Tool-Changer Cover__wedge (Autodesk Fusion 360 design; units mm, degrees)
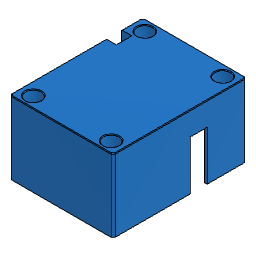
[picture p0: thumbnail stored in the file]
base_feature "Basiselement"
delete_face "Fläche löschen1"
delete_face "Fläche löschen2"
chamfer "Fase" distance 0.25
extrude "Extrusion1" sketch "unnamed" blind -0.6
extrude "Extrusion2" new body of existing geometry blind 0.6
sketch "Skizze1" plane through (0, 0, 1) normal (0, 0, 1) x axis (-1, 0, 0)
  line L1 (-19.0964, -39.75) -> (-19.75, -39.0964)
  line L2 (19.0964, -39.75) -> (-19.0964, -39.75)
  line L3 (19.75, -39.0964) -> (19.0964, -39.75)
  line L4 (19.75, 10.5964) -> (19.75, -39.0964)
  line L5 (19.0964, 11.25) -> (19.75, 10.5964)
  line L6 (-19.0964, 11.25) -> (19.0964, 11.25)
  line L7 (-19.75, 10.5964) -> (-19.0964, 11.25)
  line L8 (-19.75, -39.0964) -> (-19.75, 10.5964)
  circle C1 centre (15, -35.75) radius 3.25
  circle C2 centre (-15, 7.25) radius 3.25
  circle C3 centre (15, 7.25) radius 3.25
  circle C4 centre (-15, -35.75) radius 3.25
  circle C5 centre (15, -35.75) radius 1.6
  circle C6 centre (15, -35.75) radius 3
  circle C7 centre (-15, -35.75) radius 1.6
  circle C8 centre (-15, -35.75) radius 3
  circle C9 centre (-15, 7.25) radius 1.6
  circle C10 centre (-15, 7.25) radius 3
  circle C11 centre (15, 7.25) radius 1.6
  circle C12 centre (15, 7.25) radius 3
extrude "Extrusion3" sketch "Skizze1" profile of C5 C6 C7 C8 C9 C10 C11 C12 blind 3
extrude "Extrusion4" sketch "Skizze1" profile of C5 C7 C9 C11 blind -0.2
sketch "Skizze1" plane through (0, -11.5, 0) normal (0, -1, 0) x axis (1, 0, 0)
  line L1 (-19.2, 0.75) -> (19.2, 0.75)
  line L2 (-19.2, -27) -> (-19.2, 0.75)
  line L3 (19.2, -27) -> (-19.2, -27)
  line L4 (19.2, 0.75) -> (19.2, -27)
  line L5 (19.75, 1) -> (19.0964, 1)
  line L6 (19.0964, 1) -> (-19.0964, 1)
  line L7 (-19.0964, 1) -> (-19.75, 1)
  line L8 (-19.75, 1) -> (-20, 0.75)
  line L9 (20, 0.75) -> (19.75, 1)
  line L10 (-20, -27) -> (-19.2, -27)
  line L11 (-20, 0.75) -> (-20, -27)
  line L12 (9.5, -27) -> (19.2, -27)
  line L13 (-19.2, -27) -> (-9.5, -27)
  line L14 (20, 0.75) -> (20, -27)
  line L15 (19.2, -27) -> (20, -27)
  line L16 (8.5, -27) -> (9.5, -27)
  line L17 (-9.5, -27) -> (-8.5, -27)
  line L18 (8.5, -27) -> (-8.5, -27)
  line L19 (-16, 1) -> (-20, 1)
  line L20 (-16, -7) -> (-16, 1)
  line L21 (-20, -7) -> (-16, -7)
  line L22 (-20, 1) -> (-20, -7)
  line L23 (-16, 1) -> (-20, -7)
  line L24 (-16, -1) -> (-19, -7)
  line L25 (-15, 1) -> (-16, -1)
  line L26 (-15, 1) -> (-16, 1)
  point P24 (-19, -7)
  point P25 (-16, -1)
  point P26 (-15, 1)
  point P20 (-20, 1)
  point P21 (-16, 1)
  point P23 (-20, -7)
  horizontal L19
  vertical L20
  horizontal L21
  vertical L22
  coincident L21 P24
  coincident L20 P25
  parallel L23 L24
  coincident L6 P26
  parallel L24 L25
  perpendicular L20 L26
  dimension "d13" distance P20 P21 = 4
  dimension "d14" distance P20 P23 = 8
  dimension "d16" distance P23 P24 = 1
extrude "Extrusion5" sketch "Skizze1" profile of L1 L2 L6 L20 L21 L23 L24 L25 L26 blind -7
extrude "Extrusion6" sketch "Skizze1" profile of L1 L2 L6 L7 L8 L11 L19 L22 L23 blind -7
delete_face "Fläche löschen3"
extrude "Extrusion7" sketch "Skizze1" profile of L1 L2 L6 L7 L8 L11 L19 L20 L21 L22 L23 L24 L25 L26 blind -1
delete_face "Fläche löschen4"
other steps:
create_component "Komponente erstellen"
